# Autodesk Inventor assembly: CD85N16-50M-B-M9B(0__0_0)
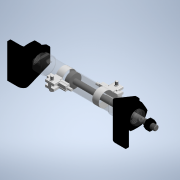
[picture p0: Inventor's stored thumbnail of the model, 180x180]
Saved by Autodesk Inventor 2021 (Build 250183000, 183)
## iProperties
Part Number: CD85N16-50M-B-M9B(0__0_0)
Catalog Web Link: www.cadenas.de
Description: C85/CD85-ISO Standard Air Cylinder:Standard Type Double Acting Single Rod
Vendor: SMC
Document SubType Name: Assembly
Designer: partserver
Manufacturer: SMC
Mass: 43.2798 g
Surface Area: 304.456 cm^2
Volume: 43.2798 cm^3
Density: 1 g/cm^3
Category: PARTsolutions
Company: SMC
PSOL_IDENT_0: {$CADENAS_DATA\23d-libs\smc_jp\actuator\standard_air_cylinder\c85\c85_asmtab.prj},310 {VTYP=3D},{STY
PSOL_IDENT_1: P=ASSTAB},{NB=CD85N16-50M-B-M9B(0__0_0)},{LINA=CD85N16-50M-B-M9B},{NN=C85/CD85},{DATE=09.12.2020 02:
PSOL_IDENT_2: 57:10},{GEOMDATE=01.09.2020 06:51:33},{VERSION=},{LINEID=90},{WBVAR=MAGNET,AUTOSW,LEAD,NUMBER,STROKE
PSOL_IDENT_3: ,POS,CUSHION,BOOT,BRACKET,POSITION,ACCESSORY,SWITCHMT,STOP,OMSC,THREAD},{WBNUMERIC=STROKE,POS}  {NB=
PSOL_IDENT_4: CD85N16-50M-B-M9B(0__0_0)},{LINA=CD85N16-50M-B-M9B},{KT=DUMMY},{ORDER=CD85N16-50M-B-M9B},{BORE=16},{
PSOL_IDENT_5: MOUNT=(N) Basic (Integral clevis)},{MOUNTX=N},{MAGNET=D},{AUTOSW=-M9B},{AUTOSWX='','(-) Without auto
PSOL_IDENT_6: switch','-M9N','M9N','-M9P','M9P','-M9B','M9B','-M9NV','M9NV','-M9PV','M9PV','-M9BV','M9BV','-M9NW'
PSOL_IDENT_7: ,'M9NW','-M9PW','M9PW','-M9BW','M9BW','-M9NWV','M9NWV','-M9PWV','M9PWV','-M9BWV','M9BWV','-M9NA','M9
PSOL_IDENT_8: NA','-M9PA','M9PA','-M9BA','M9BA','-M9NAV','M9NAV','-M9PAV','M9PAV','-M9BAV','M9BAV','-A90','A90','-
PSOL_IDENT_9: A93','A93','-A96','A96','-A90V','A90V','-A93V','A93V','-A96V','A96V','-H7C','H7C','-H7NF','H7NF','-C
PSOL_IDENT_10: 73C','C73C','-C80C','C80C','-J79C','J79C','-F79F','F79F','-A72','A72','-A72H','A72H','-A73C','A73C','
PSOL_IDENT_11: -A80C','A80C','-A79W','A79W'},{LEAD=},{LEADX='','(-) 0.5 m','M','(M) 1 m','L','(L) 3 m','Z','(Z) 5 m'
PSOL_IDENT_12: },{NUMBER=},{NUMBERX='','(-) 2 pcs','S','(S) 1 pc'},{STROKE=50},{STROKEX=[25:40./15.],50,80,100,125,
PSOL_IDENT_13: 160,200},{POS=0},{CUSHION=},{CUSHIONX= '', '(-) Rubber bumper (Standard)', 'C', '(C) Air cushion' },
PSOL_IDENT_14: {BOOT=},{BOOTX= '','N/A' },{BRACKET=M},{BRACKETX='','(-) None','L','(L) Single foot','M','(M) Double
PSOL_IDENT_15: foot','G','(G) Flange','U','(U) Trunnion','N','(N) Clevis'},{POSITION=},{POSITIONX='','N/A'},{ACCES
PSOL_IDENT_16: SORY=},{SWITCHMT=-B},{SWITCHMTX= '-A','(A) Rail mounting','-B','(B) Band mounting' },{STOP=0},{COM=-
PSOL_IDENT_17: },{OMSC=},{OMSCX='','(-) Without order','-XB6','(-XB6) Heat resistant cylinder (–10 to 150°C)','-XC6
PSOL_IDENT_18: A','(-XC6A) Stainless steel used on all standard iron parts','-XC6B','(-XC6B) Stainless steel rod en
PSOL_IDENT_19: d moving parts'},{THREAD=0},{MAX=400},{MAX1=200},{AU=M9A9},{SMIN=15},{SMINN=25},{TIF=NL},{PPATH=c85/
PSOL_IDENT_20: assembly/c85_asmsbl.prj}
NB: CD85N16-50M-B-M9B(0__0_0)
NN: C85/CD85
NT: ISO Standard Air Cylinder:Standard Type Double Acting Single Rod
NBSYN: $ORDER.($POS._$POSITION._$STOP._$THREAD.)
LINA: CD85N16-50M-B-M9B
CATALOG: SMC (JP
BORE: 16
MOUNT: (N) Basic (Integral clevis)
MAGNET: (D) With magnet
AUTOSW: M9B Solid state-General-Grommet-Indicator light:Yes-2 wire-In line
LEAD: (-) 0.5 m
NUMBER: (-) 2 pcs
STROKE: 50
POS: 0
CUSHION: (-) Rubber bumper (Standard)
BOOT: N/A
BRACKET: (M) Double foot
POSITION: N/A
ACCESSORY: (-) None
SWITCHMT: (B) Band mounting
STOP: Standard stroke
COM: -
OMSC: (-) Without order
THREAD: on
SUPPLIER: SMC
ARTICLENO: CD85N16-50M-B-M9B(0__0_0)
BOMINFO: CD85N16-50M-B-M9B
CREATOR: CADENAS GmbH
Title: CD85N16-50M-B-M9B
Author: Cadenas PARTsolutions
Comments: ISO Standard Air Cylinder:Standard Type Double Acting Single Rod
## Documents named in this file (7)
- D:\01 Paralaia\Grupos de Traballo\GT Maquetas\CAD 3D\E_AlimentaciónV1\SMC_JP_CD85N1650MBM9B000\CD85N16-50M-B-M9B(0__0_0).iam
- D:\01 Paralaia\Grupos de Traballo\GT Maquetas\CAD 3D\E_AlimentaciónV1\SMC_JP_CD85N1650MBM9B000\CD85N16-50-B-M9B(0)_BODY.ipt
- D:\01 Paralaia\Grupos de Traballo\GT Maquetas\CAD 3D\E_AlimentaciónV1\SMC_JP_CD85N1650MBM9B000\C8516-50_ROD.ipt
- D:\01 Paralaia\Grupos de Traballo\GT Maquetas\CAD 3D\E_AlimentaciónV1\SMC_JP_CD85N1650MBM9B000\C85NT16(16_).ipt
- D:\01 Paralaia\Grupos de Traballo\GT Maquetas\CAD 3D\E_AlimentaciónV1\SMC_JP_CD85N1650MBM9B000\C85SN16(16_).ipt
- D:\01 Paralaia\Grupos de Traballo\GT Maquetas\CAD 3D\E_AlimentaciónV1\SMC_JP_CD85N1650MBM9B000\D-M9B_C85_(16).ipt
- D:\01 Paralaia\Grupos de Traballo\GT Maquetas\CAD 3D\E_AlimentaciónV1\SMC_JP_CD85N1650MBM9B000\C85L16_16.ipt
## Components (9 placed, 6 different names)
1. CD85N16-50-B-M9B(0)_BODY:1
2. C8516-50_ROD:1
3. C85NT16(16_):1
4. C85SN16(16_):1
5. D-M9B_C85_(16):1
6. D-M9B_C85_(16):2
7. C85L16_16:1
8. C85L16_16:2
9. C85SN16(16_):2
